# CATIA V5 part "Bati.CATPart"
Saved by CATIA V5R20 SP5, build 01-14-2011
Part number: Bâti
Bounding box of the stored display mesh (mm): x -59.855 to 30, y -59.855 to 490, z 0 to 505
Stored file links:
  E:\IAO_2010\iao\IAO_MMS_Groupe2\IAO_MMS_Groupe2\flafosse\Catia\IAO\Bati.CATPart
  E:\IAO_2010\iao\IAO_MMS_Groupe2\IAO_MMS_Groupe2\flafosse\Catia\IAO\Synthese_IAO.CATProduct
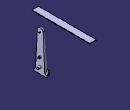
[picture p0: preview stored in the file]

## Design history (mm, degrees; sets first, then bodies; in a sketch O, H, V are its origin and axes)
Body1 (main body)
  Point1 "A": stored without definition
  Line1 "Droite AE axe bâti": stored without definition
  Sketch1 on yz-plane, origin (0, 0, 0), H (0, 1, 0), V (0, 0, 1)
    line L1 (0, 0) -> (0, 370)
    line L2 (0, 0) -> (-59.8554, 0)
    arc A1 centre (0, 342.5) radius 27.5 from (0, 370) to (-27.4641, 343.9057) ccw
    point P3 (0, 342.5)
    line L3 (-59.8554, 0) -> (-59.8554, 13)
    line L4 (-43.3988, 32.5729) -> (-27.4641, 343.9057)
    arc A2 centre (-59.3778, 33.3908) radius 16 from (-56.8249, 17.5958) to (-43.3988, 32.5729) ccw
    point P5 (-56.8249, 17.5958)
    arc A3 centre (-54.8554, 13) radius 5 from (-59.8554, 13) to (-56.8249, 17.5958) cw
    point P9 (-56.8249, 17.5958)
    radius A1 = 27.5
    radius A2 = 16
    radius A3 = 5
    length L3 = 13
    distance L3 L1 = 59.8554
    length L1 = 370
    distance P5 P9 = 0
    vertical: L1 V, L3 V
    horizontal: L2 H
    coincidence: P3 L1
    tangency: L4 A1, A2 L4, A3 L3
  Shaft1: profile Sketch1, axis Line1, angle 180
  Point2 "A": stored without definition
  Sketch2 on yz-plane, origin (0, 0, 0), H (0, 1, 0), V (0, 0, 1)
    circle A1 centre (0, 336) radius 5
    point P1 (0, 336)
    circle A2 centre (0, 136) radius 10
    point P2 (0, 136)
    point P3 (0, 56)
    circle A3 centre (0, 56) radius 10
    reference projected point E1 (0, 56) from Point6
    radius A1 = 5
    radius A2 = 10
    radius A3 = 10
    distance P2 P1 = 200
    distance P3 P2 = 80
    coincidence: P3 E1
  Pad1: profile Sketch2, direction (1, 0, 0), length 10
  Sketch3 on end face of Pad1, origin (10, 0, 0), H (0, 1, 0), V (0, 0, 1)
    circle A1 centre (0, 136) radius 5
    point P1 (0, 136)
    reference projected circle E1 centre (0, 136) radius 10 from edge [face of Pad1 from Sketch2.A2 | end face of Pad1]
    circle A2 centre (0, 56) radius 10
    reference projected circle E2 centre (0, 56) radius 10 from edge [face of Pad1 from Sketch2.A3 | end face of Pad1]
    reference projected circle E3 centre (0, 56) radius 10 from edge [face of Pad1 from Sketch2.A3 | end face of Pad1]
    radius A1 = 5
    coincidence: P1 V, A2 E2
    concentricity: A1 E1, A2 E3
  Pad2: profile Sketch3, direction (1, 0, 0), length 10
  Point3 "E": stored without definition
  Sketch4 on end face of Pad2, origin (20, 0, 0), H (0, 1, 0), V (0, 0, 1)
    circle A1 centre (0, 56) radius 5
    point P1 (0, 56)
    reference projected point E1 (0, 56) from Point3
    radius A1 = 5
    coincidence: P1 E1
  Pad3: profile Sketch4, direction (1, 0, 0), length 10
  Plane1 "Plan sup bâti": stored without definition
  Sketch5 on yz-plane, origin (0, 0, 0), H (0, 1, 0), V (0, 0, 1)
    line L1 (490, 505) -> (-90, 505)
    line L2 (-90, 505) -> (-90, 500)
    line L3 (-90, 500) -> (490, 500)
    line L4 (490, 500) -> (490, 505)
    length L2 = 5
    distance L4 L2 = 580
    distance L4 V = 490
    distance H L3 = 500
    horizontal: L1 H, L3 H
    vertical: L2 V, L4 V
  Pad4: profile Sketch5, direction (1, 0, 0), length 30, mirrored extent
  Point4 "G": stored without definition
  Sketch6 on face of Pad4 from Sketch5.L1, origin (0, 0, 505), H (1, 0, 0), V (0, 1, 0)
    line L1 (0, -90) -> (0, 490)
    point P1 (0, -90)
    point P2 (0, 490)
    reference projected line E1 (30, 490) -> (-30, 490) from edge [face of Pad4 from Sketch5.L4 | face of Pad4 from Sketch5.L1]
    reference projected line E2 (30, -90) -> (-30, -90) from edge [face of Pad4 from Sketch5.L1 | face of Pad4 from Sketch5.L2]
    coincidence: P1 V, P2 E1, P1 E2
    vertical: L1 V
  Sketch7 on face of Pad4 from Sketch5.L1, origin (0, 0, 505), H (1, 0, 0), V (0, 1, 0)
    line L1 (-30, -45) -> (30, -45)
    line L2 (30, -45) -> (30, -90)
    line L3 (30, -90) -> (-30, -90)
    line L4 (-30, -90) -> (-30, -45)
    reference projected line E1 (-30, -90) -> (30, -90) from edge [face of Pad4 from Sketch5.L2 | face of Pad4 from Sketch5.L1]
    reference projected line E2 (30, 490) -> (30, -10) from edge [face of Pad4 from Sketch5.L1 | end face of Pad4]
    length L4 = 45
    length L1 = 60
    horizontal: L1 H, L3 H
    vertical: L2 V, L4 V
    coincidence: L3 E1, L2 E2
  Pocket1: profile Sketch7, direction (0, 0, -1), through (limit type 6)
  Point5 "D": stored without definition
  Point6 "E": stored without definition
